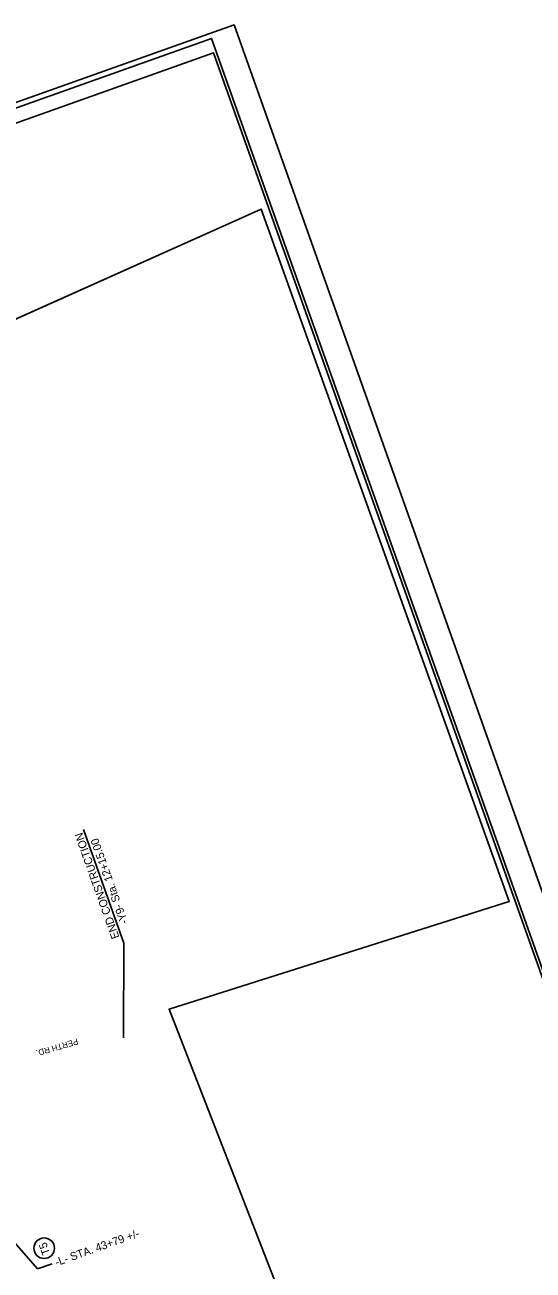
# Model space of a CAD drawing. Extents: x 1615843 to 1617934, y 901966 to 903921.
# Drawn here: x 1616697 to 1617141, y 902832 to 903921 of the extents above; entities that cross this region are included whole.
import ezdxf

# ---------------------------------------------------------------- set-up
doc = ezdxf.new("R2010")
doc.units = 0
for name, color, linetype in [('Default', 7, 'Continuous'), ('Matchline', 7, 'Continuous'), ('Sheet Border Standard 30in CELL', 7, 'Continuous'), ('Sheet Clip Boundary CELL', 7, 'Continuous'), ('Sheet Plan CELL', 7, 'Continuous'), ('Sheet Plot Border Inside CELL', 7, 'Continuous'), ('Sheet Plot Border Outside CELL', 7, 'Continuous'), ('Sheet Sticker Incomplete CELL', 7, 'Continuous')]:
    doc.layers.add(name, color=color, linetype=linetype)

msp = doc.modelspace()

# ---------------------------------------------------------------- linework, layer by layer
at = {"layer": 'Matchline'}
msp.add_line((1615953.1, 903334.3), (1616903.3, 903759.8), dxfattribs=at)
at = {"layer": 'Sheet Border Standard 30in CELL'}
msp.add_lwpolyline([(1615872.3, 903544.7), (1616374.7, 902131.4), (1617364.1, 902483.1), (1616861.6, 903896.5)], close=True, dxfattribs=at)
at = {"layer": 'Sheet Clip Boundary CELL'}
for p, q in [((1616607.7, 902947), (1616707.6, 902832.9)), ((1616707.6, 902832.9), (1616720.5, 902837.4))]:
    msp.add_line(p, q, dxfattribs=at)
msp.add_circle((1616713.4, 902851), 9.01, dxfattribs=at)
at = {"layer": 'Sheet Plan CELL'}
for p, q in [((1616783.1, 903117.9), (1616747.8, 903217.3)), ((1616782.7, 903035.1), (1616783.1, 903117.9))]:
    msp.add_line(p, q, dxfattribs=at)
at = {"layer": 'Sheet Plot Border Inside CELL'}
msp.add_lwpolyline([(1615865.7, 903555.7), (1616423.9, 901985.4), (1617418.1, 902338.9), (1616859.8, 903909.1)], close=True, dxfattribs=at)
at = {"layer": 'Sheet Plot Border Outside CELL'}
msp.add_lwpolyline([(1615843, 903552.4), (1616407.1, 901965.7), (1617443.6, 902334.1), (1616879.5, 903920.8)], close=True, dxfattribs=at)
at = {"layer": 'Sheet Sticker Incomplete CELL'}
msp.add_lwpolyline([(1616920.6, 902383), (1616299.5, 902356.1), (1615953.1, 903334.3), (1616369.2, 903520.6), (1616903.3, 903759.8), (1617120.2, 903154.3), (1616822.6, 903060), (1617083.5, 902390)], close=True, dxfattribs=at)

# ---------------------------------------------------------------- texts
at = {"layer": 'Default'}
msp.add_text('PERTH RD.', height=5.25, rotation=196.0521, dxfattribs=at).set_placement((1616742.2, 903034.5))
at = {"layer": 'Sheet Clip Boundary CELL'}
for s, rotation, p in [('-L- STA. 43+79 +/-', 19.5707, (1616724.3, 902835.2)), ('T5', 109.5399, (1616718.7, 902846.5))]:
    msp.add_text(s, height=7, rotation=rotation, dxfattribs=at).set_placement(p)
at = {"layer": 'Sheet Plan CELL'}
for s, p in [('END CONSTRUCTION', (1616779.3, 903123)), ('-Y9- Sta. 12+15.00', (1616786.8, 903135.9))]:
    msp.add_text(s, height=7, rotation=109.5707, dxfattribs=at).set_placement(p)

doc.saveas('drawing.dxf')
